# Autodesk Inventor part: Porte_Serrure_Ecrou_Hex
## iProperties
Created: 2009-01
Part Number: Porte_Serrure_Ecrou_Hex
Document SubType Name: Modeling
Designer: claivier
Author: claivier
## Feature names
1. Base1
